// Mitsubishi GX Works2 project: MODBUS通讯485   PLC: FX3U/FX3UC

PROGRAM MAIN
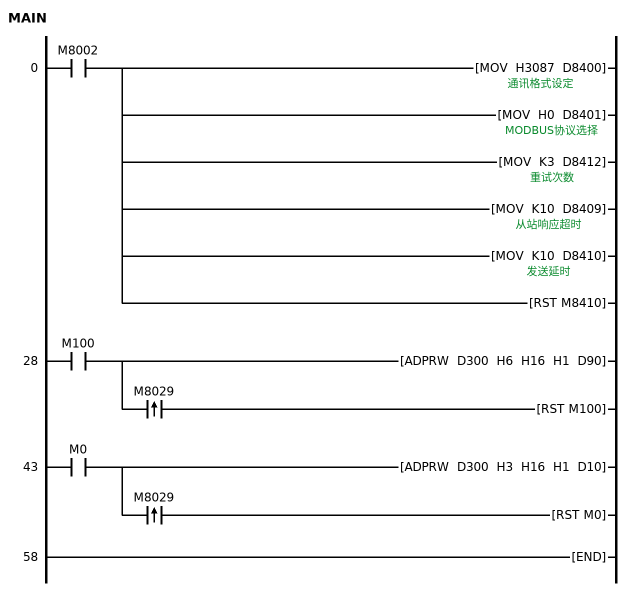
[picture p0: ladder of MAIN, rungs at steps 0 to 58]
0     LD      M8002
      MOV     H3087 D8400  ; 通讯格式设定
      MOV     H0 D8401  ; MODBUS协议选择
        [note] 主站
      MOV     K3 D8412  ; 重试次数
      MOV     K10 D8409  ; 从站响应超时
      MOV     K10 D8410  ; 发送延时
      RST     M8410
        [note] 使用ADPRW指令
28    LD      M100
      ADPRW   D300 H6 H16 H1 D90
        [note] 写
      ANDP    M8029
      RST     M100
43    LD      M0
      ADPRW   D300 H3 H16 H1 D10
        [note] 读
      ANDP    M8029
      RST     M0
58    END
END_PROGRAM
